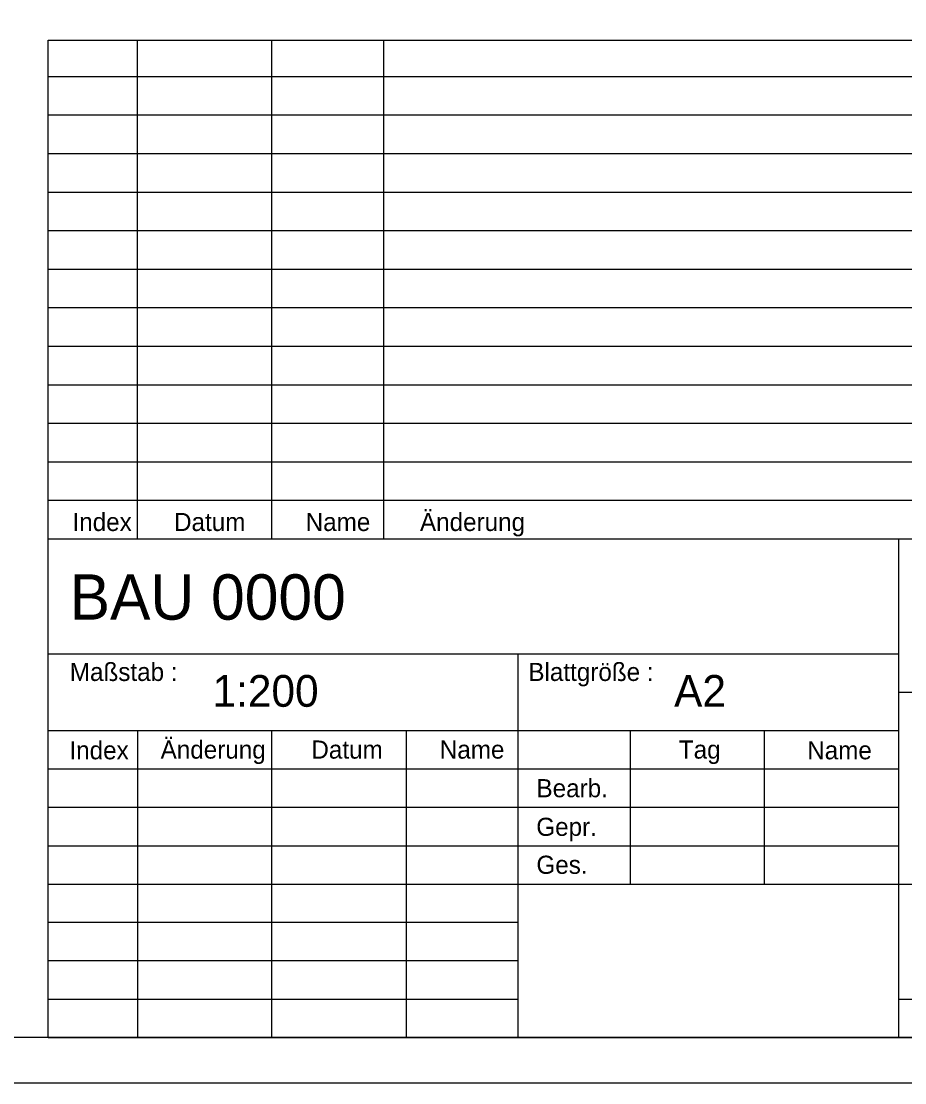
# Model space of a CAD drawing. Extents: x 0 to 119, y 0 to 84.
# Drawn here: x 81.63 to 101.13, y 0 to 23.42 of the extents above; entities that cross this region are included whole.
import ezdxf

# ---------------------------------------------------------------- set-up
doc = ezdxf.new("R2010")
doc.units = 0
doc.layers.add('90_Plankopf', color=7, linetype='Continuous')

msp = doc.modelspace()

# ---------------------------------------------------------------- linework, layer by layer
at = {"layer": '90_Plankopf'}
for p, q in [((82.224, 11.998), (82.224, 22.996)), ((82.224, 22.996), (117.8, 22.996)), ((84.2, 11.998), (84.2, 22.996)), ((87.165, 11.998), (87.165, 22.996)), ((89.636, 11.998), (89.636, 22.996)), ((82.224, 22.198), (117.8, 22.198)), ((82.224, 21.348), (117.8, 21.348)), ((82.224, 20.498), (117.8, 20.498)), ((82.224, 19.648), (117.8, 19.648)), ((82.224, 18.798), (117.8, 18.798)), ((82.224, 17.948), (117.8, 17.948)), ((82.224, 17.098), (117.8, 17.098)), ((82.224, 16.248), (117.8, 16.248)), ((82.224, 15.398), (117.8, 15.398)), ((82.224, 14.548), (117.8, 14.548)), ((82.224, 13.698), (117.8, 13.698)), ((82.224, 12.848), (117.8, 12.848)), ((82.224, 11.998), (117.8, 11.998)), ((82.224, 1), (82.224, 11.998)), ((82.224, 11.998), (117.8, 11.998)), ((101, 1), (101, 11.998)), ((82.224, 9.46), (101, 9.46)), ((92.6, 1), (92.6, 9.46)), ((101, 8.614), (117.8, 8.614)), ((82.224, 7.774), (101, 7.774)), ((84.2, 7.768), (84.2, 1)), ((87.165, 1), (87.165, 7.768)), ((90.13, 1), (90.13, 7.768)), ((95.071, 7.768), (95.071, 4.384)), ((98.036, 4.384), (98.036, 7.768)), ((82.224, 6.926), (101, 6.926)), ((82.224, 6.076), (101, 6.076)), ((82.224, 5.23), (101, 5.23)), ((82.224, 4.384), (101, 4.384)), ((82.224, 4.384), (101, 4.384)), ((92.6, 4.384), (101, 4.384)), ((101, 4.384), (117.8, 4.384)), ((92.6, 3.538), (82.224, 3.538)), ((92.6, 2.692), (82.224, 2.692)), ((82.224, 1.846), (92.6, 1.846)), ((101, 1.846), (117.8, 1.846)), ((117.8, 1), (82.224, 1)), ((82.224, 1), (92.6, 1)), ((84.56, 1), (117.8, 1)), ((84.56, 1), (117.8, 1))]:
    msp.add_line(p, q, dxfattribs=at)
for points in [[(0, 0), (118.8, 0), (118.8, 84), (0, 84)], [(5, 83), (117.8, 83), (117.8, 1), (5, 1)]]:
    msp.add_lwpolyline(points, close=True, dxfattribs=at)

# ---------------------------------------------------------------- texts
for s, height, p in [('Änderung', 0.4, (90.431, 12.171)), ('Index', 0.4, (82.761, 12.171)), ('Datum', 0.4, (85.003, 12.171)), ('Name', 0.4, (87.908, 12.171)), ('BAU 0000      ', 1, (82.698, 10.215)), ('Maßstab :', 0.4, (82.703, 8.863)), ('Blattgröße :', 0.39998, (92.823, 8.863)), ('1:200    ', 0.7, (85.852, 8.294)), ('A2       ', 0.7, (96.04, 8.294)), ('Index', 0.4, (82.694, 7.135)), ('Änderung', 0.4, (84.707, 7.15)), ('Datum', 0.4, (88.034, 7.15)), ('Name', 0.4, (90.869, 7.15)), ('Tag', 0.4, (96.145, 7.15)), ('Name', 0.4, (98.978, 7.135)), ('Bearb.', 0.4, (93.003, 6.298)), ('Gepr.', 0.4, (92.998, 5.446)), ('Ges.', 0.4, (93.001, 4.609))]:
    msp.add_text(s, height=height, dxfattribs=at).set_placement(p)

doc.saveas('drawing.dxf')
